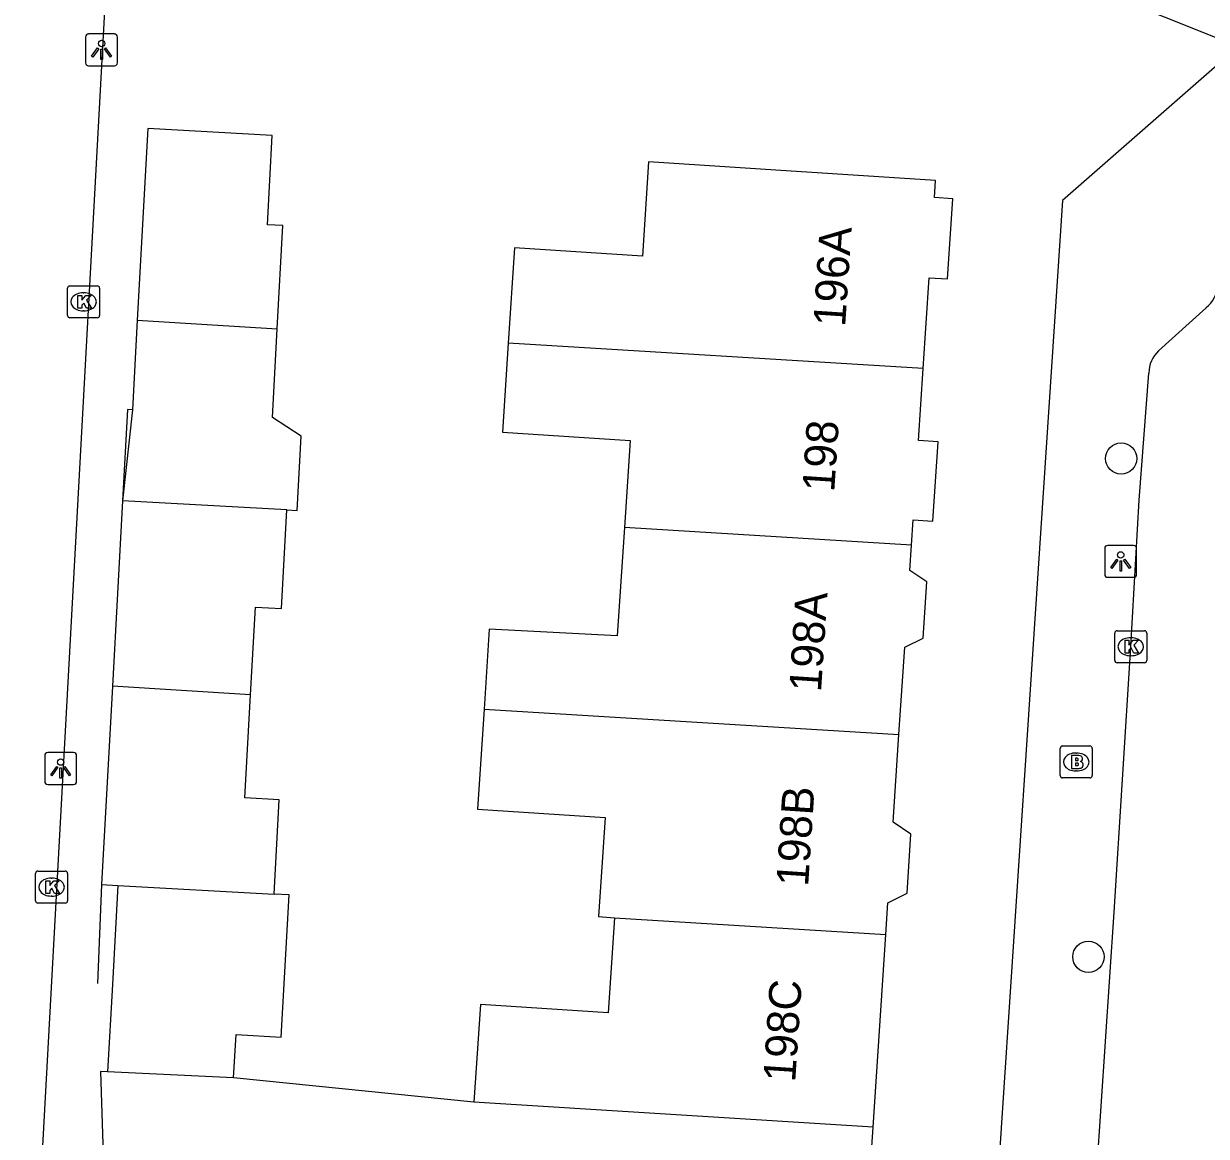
# Model space of a CAD drawing. Extents: x 160107 to 160928, y 382056 to 382918.
# Drawn here: x 160507.91 to 160544.87, y 382371.41 to 382406.18 of the extents above; entities that cross this region are included whole.
import ezdxf

# ---------------------------------------------------------------- set-up
doc = ezdxf.new("R2010")
doc.units = 0
for name, color, linetype in [('IMGEO_Boom', 7, 'Continuous'), ('IMGEO_Brandkraan', 7, 'Continuous'), ('IMGEO_Kolk', 7, 'Continuous'), ('IMGEO_Lichtpunt', 7, 'Continuous'), ('IMGEO_Muur', 7, 'Continuous'), ('IMGEO_Pand', 7, 'Continuous'), ('IMGEO_Pand_nummerreeks', 7, 'Continuous'), ('IMGEO_Rijbaan_lokaal_open', 7, 'Continuous'), ('IMGEO_Voetpad_open', 7, 'Continuous')]:
    doc.layers.add(name, color=color, linetype=linetype)

msp = doc.modelspace()

# ---------------------------------------------------------------- linework, layer by layer
at = {"layer": 'IMGEO_Boom'}
for centre in [(160542.208, 382392.591), (160541.184, 382377.019)]:
    msp.add_circle(centre, 0.489, dxfattribs=at)
at = {"layer": 'IMGEO_Brandkraan'}
for p, q in [((160540.304, 382382.681), (160540.304, 382383.533)), ((160540.379, 382383.607), (160541.231, 382383.607)), ((160540.792, 382383.387), (160540.817, 382383.387)), ((160541.305, 382383.533), (160541.305, 382382.681)), ((160541.231, 382382.607), (160540.379, 382382.607)), ((160540.815, 382382.827), (160540.79, 382382.827))]:
    msp.add_line(p, q, dxfattribs=at)
for points in [[(160540.304, 382382.681), (160540.304, 382383.533)], [(160540.379, 382383.607), (160541.231, 382383.607)], [(160540.652, 382383.307), (160540.652, 382382.907), (160540.865, 382382.907)], [(160540.883, 382383.307), (160540.652, 382383.307)], [(160541.305, 382383.533), (160541.305, 382382.681)], [(160540.831, 382383.226), (160540.777, 382383.226), (160540.777, 382383.15)], [(160540.777, 382383.15), (160540.83, 382383.15)], [(160540.839, 382383.074), (160540.777, 382383.074), (160540.777, 382382.993)], [(160540.777, 382382.993), (160540.839, 382382.993)], [(160541.231, 382382.607), (160540.379, 382382.607)]]:
    msp.add_lwpolyline(points, dxfattribs=at)
for centre, radius, start, end in [((160540.381, 382383.531), 0.0765, 91.552, 178.448), ((160540.381, 382383.531), 0.0765, 91.552, 178.448), ((160540.887, 382383.162), 0.145, 59.4692, 91.5367), ((160541.229, 382383.531), 0.0765, 1.552, 88.448), ((160541.229, 382383.531), 0.0765, 1.552, 88.448), ((160540.832, 382383.188), 0.0379, 267.8285, 90.9355), ((160540.84, 382383.033), 0.0404, 269.8759, 90.5077), ((160540.871, 382383.158), 0.251, 268.6676, 293.5347), ((160540.912, 382383.209), 0.0922, 285.5137, 58.1501), ((160540.917, 382383.017), 0.105, 301.3115, 78.989), ((160540.381, 382382.683), 0.0765, 181.552, 268.448), ((160540.381, 382382.683), 0.0765, 181.552, 268.448), ((160541.229, 382382.683), 0.0765, 271.552, 358.448), ((160541.229, 382382.683), 0.0765, 271.552, 358.448)]:
    msp.add_arc(centre, radius, start, end, dxfattribs=at)
for centre, major_axis, ratio, start_param, end_param in [((160540.791, 382383.107), (-0.387, 0.002), 0.722429, 4.712389, 7.853982), ((160540.816, 382383.107), (-0.39, 0.002), 0.717154, 1.570796, 4.712389)]:
    msp.add_ellipse(centre, major_axis=major_axis, ratio=ratio, start_param=start_param, end_param=end_param, dxfattribs=at)
at = {"layer": 'IMGEO_Kolk'}
for p, q in [((160509.281, 382397.061), (160509.281, 382397.913)), ((160509.356, 382397.987), (160510.208, 382397.987)), ((160509.769, 382397.767), (160509.794, 382397.767)), ((160510.282, 382397.913), (160510.282, 382397.061)), ((160510.208, 382396.987), (160509.356, 382396.987)), ((160509.792, 382397.207), (160509.767, 382397.207)), ((160542.009, 382386.283), (160542.009, 382387.135)), ((160542.084, 382387.209), (160542.936, 382387.209)), ((160543.01, 382387.135), (160543.01, 382386.283)), ((160542.497, 382386.989), (160542.522, 382386.989)), ((160542.52, 382386.429), (160542.495, 382386.429)), ((160542.936, 382386.209), (160542.084, 382386.209)), ((160508.281, 382378.77), (160508.281, 382379.622)), ((160508.356, 382379.696), (160509.208, 382379.696)), ((160509.282, 382379.622), (160509.282, 382378.77)), ((160508.769, 382379.476), (160508.794, 382379.476)), ((160508.792, 382378.916), (160508.767, 382378.916)), ((160509.208, 382378.696), (160508.356, 382378.696))]:
    msp.add_line(p, q, dxfattribs=at)
for points in [[(160509.281, 382397.061), (160509.281, 382397.913)], [(160509.356, 382397.987), (160510.208, 382397.987)], [(160510.282, 382397.913), (160510.282, 382397.061)], [(160509.602, 382397.687), (160509.725, 382397.687), (160509.725, 382397.536), (160509.855, 382397.687), (160510.019, 382397.687), (160509.873, 382397.536), (160510.026, 382397.287), (160509.874, 382397.287), (160509.789, 382397.451), (160509.725, 382397.384), (160509.725, 382397.287), (160509.602, 382397.287), (160509.602, 382397.687)], [(160510.208, 382396.987), (160509.356, 382396.987)], [(160542.009, 382386.283), (160542.009, 382387.135)], [(160542.084, 382387.209), (160542.936, 382387.209)], [(160543.01, 382387.135), (160543.01, 382386.283)], [(160542.33, 382386.909), (160542.453, 382386.909), (160542.453, 382386.758), (160542.583, 382386.909), (160542.747, 382386.909), (160542.601, 382386.758), (160542.754, 382386.509), (160542.602, 382386.509), (160542.517, 382386.673), (160542.453, 382386.606), (160542.453, 382386.509), (160542.33, 382386.509), (160542.33, 382386.909)], [(160542.936, 382386.209), (160542.084, 382386.209)], [(160508.281, 382378.77), (160508.281, 382379.622)], [(160508.356, 382379.696), (160509.208, 382379.696)], [(160509.282, 382379.622), (160509.282, 382378.77)], [(160508.602, 382379.396), (160508.725, 382379.396), (160508.725, 382379.245), (160508.855, 382379.396), (160509.019, 382379.396), (160508.873, 382379.245), (160509.026, 382378.996), (160508.874, 382378.996), (160508.789, 382379.16), (160508.725, 382379.093), (160508.725, 382378.996), (160508.602, 382378.996), (160508.602, 382379.396)], [(160509.208, 382378.696), (160508.356, 382378.696)]]:
    msp.add_lwpolyline(points, dxfattribs=at)
for centre, start, end in [((160509.358, 382397.911), 91.552, 178.448), ((160509.358, 382397.911), 91.552, 178.448), ((160510.206, 382397.911), 1.552, 88.448), ((160510.206, 382397.911), 1.552, 88.448), ((160509.358, 382397.063), 181.552, 268.448), ((160509.358, 382397.063), 181.552, 268.448), ((160510.206, 382397.063), 271.552, 358.448), ((160510.206, 382397.063), 271.552, 358.448), ((160542.086, 382387.133), 91.552, 178.448), ((160542.086, 382387.133), 91.552, 178.448), ((160542.934, 382387.133), 1.552, 88.448), ((160542.934, 382387.133), 1.552, 88.448), ((160542.086, 382386.285), 181.552, 268.448), ((160542.086, 382386.285), 181.552, 268.448), ((160542.934, 382386.285), 271.552, 358.448), ((160542.934, 382386.285), 271.552, 358.448), ((160508.358, 382379.62), 91.552, 178.448), ((160508.358, 382379.62), 91.552, 178.448), ((160509.206, 382379.62), 1.552, 88.448), ((160509.206, 382379.62), 1.552, 88.448), ((160508.358, 382378.772), 181.552, 268.448), ((160508.358, 382378.772), 181.552, 268.448), ((160509.206, 382378.772), 271.552, 358.448), ((160509.206, 382378.772), 271.552, 358.448)]:
    msp.add_arc(centre, 0.0765, start, end, dxfattribs=at)
for centre, major_axis, ratio, start_param, end_param in [((160509.768, 382397.487), (-0.387, 0.002), 0.722429, 4.712389, 7.853982), ((160509.793, 382397.487), (-0.39, 0.002), 0.717154, 1.570796, 4.712389), ((160542.496, 382386.709), (-0.387, 0.002), 0.722429, 4.712389, 7.853982), ((160542.521, 382386.709), (-0.39, 0.002), 0.717154, 1.570796, 4.712389), ((160508.768, 382379.196), (-0.387, 0.002), 0.722429, 4.712389, 7.853982), ((160508.793, 382379.196), (-0.39, 0.002), 0.717154, 1.570796, 4.712389)]:
    msp.add_ellipse(centre, major_axis=major_axis, ratio=ratio, start_param=start_param, end_param=end_param, dxfattribs=at)
at = {"layer": 'IMGEO_Lichtpunt'}
for p, q in [((160510.749, 382405.858), (160509.941, 382405.858)), ((160510.749, 382405.858), (160509.941, 382405.858)), ((160509.847, 382405.763), (160509.847, 382404.956)), ((160509.847, 382405.763), (160509.847, 382404.956)), ((160510.843, 382404.956), (160510.843, 382405.763)), ((160510.843, 382404.956), (160510.843, 382405.763)), ((160509.941, 382404.862), (160510.749, 382404.862)), ((160509.941, 382404.862), (160510.749, 382404.862)), ((160541.697, 382389.78), (160541.697, 382388.973)), ((160541.697, 382389.78), (160541.697, 382388.973)), ((160542.599, 382389.875), (160541.791, 382389.875)), ((160542.599, 382389.875), (160541.791, 382389.875)), ((160542.693, 382388.973), (160542.693, 382389.78)), ((160542.693, 382388.973), (160542.693, 382389.78)), ((160541.791, 382388.879), (160542.599, 382388.879)), ((160541.791, 382388.879), (160542.599, 382388.879)), ((160508.568, 382383.305), (160508.568, 382382.498)), ((160508.568, 382383.305), (160508.568, 382382.498)), ((160509.47, 382383.4), (160508.662, 382383.4)), ((160509.47, 382383.4), (160508.662, 382383.4)), ((160509.564, 382382.498), (160509.564, 382383.305)), ((160509.564, 382382.498), (160509.564, 382383.305)), ((160508.662, 382382.404), (160509.47, 382382.404)), ((160508.662, 382382.404), (160509.47, 382382.404))]:
    msp.add_line(p, q, dxfattribs=at)
for points in [[(160510.221, 382405.427), (160510.26, 382405.399), (160510.072, 382405.137), (160510.034, 382405.164), (160510.221, 382405.427)], [(160510.323, 382405.379), (160510.37, 382405.379), (160510.37, 382405.057), (160510.323, 382405.057), (160510.323, 382405.379)], [(160510.433, 382405.399), (160510.471, 382405.426), (160510.658, 382405.164), (160510.619, 382405.136), (160510.433, 382405.399)], [(160542.071, 382389.444), (160542.11, 382389.416), (160541.922, 382389.154), (160541.884, 382389.181), (160542.071, 382389.444)], [(160542.173, 382389.396), (160542.22, 382389.396), (160542.22, 382389.074), (160542.173, 382389.074), (160542.173, 382389.396)], [(160542.283, 382389.416), (160542.321, 382389.443), (160542.508, 382389.181), (160542.469, 382389.153), (160542.283, 382389.416)], [(160508.942, 382382.969), (160508.981, 382382.941), (160508.793, 382382.679), (160508.755, 382382.706), (160508.942, 382382.969)], [(160509.154, 382382.941), (160509.192, 382382.968), (160509.379, 382382.706), (160509.34, 382382.678), (160509.154, 382382.941)], [(160509.044, 382382.921), (160509.091, 382382.921), (160509.091, 382382.599), (160509.044, 382382.599), (160509.044, 382382.921)]]:
    msp.add_lwpolyline(points, dxfattribs=at)
for centre in [(160510.346, 382405.561), (160542.196, 382389.578), (160509.067, 382383.103)]:
    msp.add_circle(centre, 0.0994, dxfattribs=at)
for centre, start, end in [((160509.941, 382405.763), 90, 180), ((160509.941, 382405.763), 90, 180), ((160510.749, 382405.763), 0, 90), ((160510.749, 382405.763), 0, 90), ((160509.941, 382404.956), 180, 270), ((160509.941, 382404.956), 180, 270), ((160510.749, 382404.956), 270, 0), ((160510.749, 382404.956), 270, 360), ((160541.791, 382389.78), 90, 180), ((160541.791, 382389.78), 90, 180), ((160542.599, 382389.78), 0, 90), ((160542.599, 382389.78), 0, 90), ((160541.791, 382388.973), 180, 270), ((160541.791, 382388.973), 180, 270), ((160542.599, 382388.973), 270, 0), ((160542.599, 382388.973), 270, 360), ((160508.662, 382383.305), 90, 180), ((160508.662, 382383.305), 90, 180), ((160509.47, 382383.305), 0, 90), ((160509.47, 382383.305), 0, 90), ((160508.662, 382382.498), 180, 270), ((160508.662, 382382.498), 180, 270), ((160509.47, 382382.498), 270, 0), ((160509.47, 382382.498), 270, 360)]:
    msp.add_arc(centre, 0.0946, start, end, dxfattribs=at)
at = {"layer": 'IMGEO_Muur'}
for points in [[(160511.307, 382394.115), (160511.003, 382391.266)], [(160510.344, 382379.275), (160510.219, 382376.181)]]:
    msp.add_lwpolyline(points, dxfattribs=at)
at = {"layer": 'IMGEO_Pand'}
for points in [[(160531.994, 382415.99), (160531.848, 382413.645), (160538.173, 382413.251), (160537.889, 382408.7), (160541.232, 382407.327), (160545.873, 382405.467)], [(160515.835, 382396.642), (160516.012, 382399.868), (160515.526, 382399.895), (160515.68, 382402.69), (160511.79, 382402.904), (160511.461, 382396.91)], [(160536.022, 382395.404), (160536.209, 382398.241), (160536.782, 382398.203), (160536.947, 382400.706), (160536.375, 382400.744), (160536.41, 382401.276), (160531.421, 382401.605), (160527.441, 382401.867), (160527.245, 382398.914), (160523.253, 382399.177), (160523.056, 382396.199)], [(160511.461, 382396.91), (160511.307, 382394.115), (160511.16, 382394.123), (160511.003, 382391.266)], [(160511.461, 382396.91), (160515.835, 382396.642)], [(160516.138, 382390.984), (160516.458, 382390.966), (160516.586, 382393.293), (160515.683, 382393.874), (160515.835, 382396.642)], [(160523.056, 382396.199), (160522.872, 382393.419), (160526.863, 382393.155), (160526.683, 382390.43)], [(160536.022, 382395.404), (160523.056, 382396.199)], [(160535.657, 382389.881), (160535.71, 382390.676), (160536.321, 382390.635), (160536.485, 382393.113), (160535.873, 382393.153), (160536.022, 382395.404)], [(160511.003, 382391.266), (160510.685, 382385.473)], [(160516.138, 382390.984), (160511.003, 382391.266)], [(160515.004, 382385.208), (160515.154, 382387.944), (160515.969, 382387.9), (160516.138, 382390.984)], [(160526.683, 382390.43), (160526.673, 382390.284), (160526.459, 382387.054), (160522.463, 382387.26), (160522.298, 382384.761)], [(160535.657, 382389.881), (160526.683, 382390.43)], [(160535.266, 382383.966), (160535.447, 382386.694), (160536.018, 382386.975), (160536.134, 382388.734), (160535.605, 382389.087), (160535.657, 382389.881)], [(160510.685, 382385.473), (160510.344, 382379.275), (160510.854, 382379.247)], [(160515.004, 382385.208), (160510.685, 382385.473)], [(160515.735, 382378.978), (160515.897, 382381.929), (160514.827, 382381.988), (160515.004, 382385.208)], [(160522.298, 382384.761), (160522.091, 382381.633), (160526.082, 382381.369), (160525.877, 382378.275), (160526.375, 382378.239)], [(160522.298, 382384.761), (160535.266, 382383.966)], [(160534.853, 382377.72), (160534.918, 382378.71), (160535.519, 382379.005), (160535.641, 382380.851), (160535.085, 382381.223), (160535.266, 382383.966)], [(160510.854, 382379.247), (160510.684, 382376.155), (160510.533, 382373.422)], [(160510.854, 382379.247), (160515.735, 382378.978)], [(160514.472, 382373.239), (160514.547, 382374.589), (160515.959, 382374.511), (160516.204, 382378.952), (160515.735, 382378.978)], [(160526.375, 382378.239), (160526.178, 382375.268), (160522.186, 382375.531), (160521.983, 382372.472)], [(160526.375, 382378.239), (160534.853, 382377.72)], [(160534.454, 382371.69), (160534.853, 382377.72)], [(160510.533, 382373.422), (160510.31, 382373.432), (160510.504, 382367.584)], [(160514.472, 382373.239), (160510.533, 382373.422)], [(160521.983, 382372.472), (160514.472, 382373.239)], [(160534.454, 382371.69), (160521.983, 382372.472)], [(160534.068, 382365.836), (160534.454, 382371.69)]]:
    msp.add_lwpolyline(points, dxfattribs=at)
at = {"layer": 'IMGEO_Rijbaan_lokaal_open'}
for points in [[(160507.91, 382360.033), (160510.596, 382409.264)], [(160543.377, 382395.959), (160544.868, 382397.305)], [(160540.908, 382362.241), (160541.991, 382378.413), (160542.511, 382386.709), (160542.772, 382391.292), (160543.074, 382395.262)]]:
    msp.add_lwpolyline(points, dxfattribs=at)
for centre, radius, start, end in [((160544.276, 382398.043), 0.946, 308.7542, 356.5093), ((160544.037, 382395.258), 0.963, 133.2679, 179.741)]:
    msp.add_arc(centre, radius, start, end, dxfattribs=at)
at = {"layer": 'IMGEO_Voetpad_open'}
msp.add_lwpolyline([(160545.873, 382405.467), (160540.377, 382400.659), (160537.4, 382355.596)], dxfattribs=at)

# ---------------------------------------------------------------- texts
at = {"layer": 'IMGEO_Pand_nummerreeks'}
for s, rotation, p in [('196A', 86.2162, (160533.582, 382396.693)), ('198', 86.2274, (160533.241, 382391.527)), ('198A', 86.2187, (160532.828, 382385.277)), ('198B', 86.2089, (160532.425, 382379.197)), ('198C', 86.221, (160532.021, 382373.084))]:
    msp.add_text(s, height=1, rotation=rotation, dxfattribs=at).set_placement(p)

doc.saveas('drawing.dxf')
